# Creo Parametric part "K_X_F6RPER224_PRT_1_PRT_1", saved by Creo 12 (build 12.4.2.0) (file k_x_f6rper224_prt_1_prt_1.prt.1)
Units: Custom; MM, KILOGRAM, SECS

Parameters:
  PTC_WM_ITERATION = "0"
  PTC_WM_VERSION = "-.0"
  PTC_WM_LIFECYCLE_STATE = "In Work"
  PTC_WM_LIFECYCLE = "MO_CADDocument"
  PTC_WM_CREATED_BY = "Maximilian Roepper (Z0017RMS: MO)"
  PTC_WM_CREATED_ON = "18-Sep-26 11:36:42 AM"
  PTC_WM_MODIFIED_BY = "Maximilian Roepper (Z0017RMS: MO)"
  PTC_WM_MODIFIED_ON = "18-Sep-26 11:36:46 AM"
  PDMLINKNUMBER = "PDM000071455180"
  PTC_WM_NAME = "k_x_f6rper224_prt_1_prt_1.prt"
  PTC_WM_NUMBER = "PDM000071455180"

Other parameters: WEIGHT, WEIGHT_FACTOR, WEIGHT_ADD, _MASS_TEMP, _DIFF_TEMP, MC_ERRORS, SUPPLIER

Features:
  1. coordinate system
  2. datum plane "PRT_YZ"
  3. datum plane "PRT_XY"
  4. datum plane "PRT_XZ"
  5. coordinate system
  6. datum axis
  7. datum axis
  8. datum axis
  9. coordinate system
  10. imported feature
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
Other named items: PRT, SIEMENS_MO, DRW_VIEW_ORG, PRT_X, PRT_Y, PRT_Z, CS0, ROUGH_GROB

Layers: 00_STD_CSYS-KSYS, 01_STD_PLANES-EBENEN, 02_STD_AXES-ACHSEN, 03_STD_CSYS-KSYS, 24_IMPORT_FEAT-IMPORT_KE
